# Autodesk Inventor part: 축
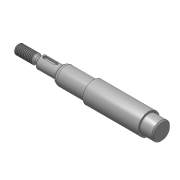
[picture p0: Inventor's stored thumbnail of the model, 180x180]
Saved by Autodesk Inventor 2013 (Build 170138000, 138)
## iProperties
Created: 2015-11
Part Number: 축
Material: 강철, 연강
Document SubType Name: Modeling
Designer: mduedu
Density: 1 g/cm^3
Author: mduedu
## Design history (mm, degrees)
sketch "스케치1"
  geometry: L1 (-86, 0)-(86, 0); L2 (-86, 0)-(-86, 4); L3 (-86, 4)-(-70.732, 4); L4 (-70.732, 4)-(-69, 3); L5 (-69, 3)-(-67, 3); L6 (-67, 3)-(-67, 5); L7 (-67, 5)-(-49, 5); L8 (-49, 5)-(-49, 6.55); L9 (-47.355, 7.5)-(-23, 7.5); L10 (-23, 7.5)-(-23, 9); L11 (0, 0)-(0, 9); L12 (86, 4)-(70.732, 4); L13 (70.732, 4)-(69, 3); L14 (69, 3)-(67, 3); L15 (67, 3)-(67, 5); L16 (67, 5)-(49, 5); L17 (23, 7.5)-(23, 9); L18 (86, 0)-(86, 4); L19 (-23, 9)-(23, 9); L20 (-49, 6.55)-(-47.355, 7.5); L21 (47.355, 7.5)-(23, 7.5); L22 (49, 6.55)-(47.355, 7.5); L23 (49, 5)-(49, 6.55); 1 further point
  constraints: 46 end point, 10 symmetric about line, 6 perpendicular, 5 parallel, 2 midpoint, 1 coincident, 1 horizontal
  dimensions: "d0" = 172 distance of L1.start L1.end (derived); "d1" = 8 diameter of L3 L1; "d2" = 30 deg angle of L4 L5; "d3" = 6 diameter of L5 L1; "d4" = 10 diameter of L7 L1; "d5" = 15 diameter of L9 L1; "d6" = 18 diameter of L19 L1; "d8" = 18 distance of L6.end L7.end; "d9" = 46 distance of L10.end L17.end; "d10" = 2 distance of L4.end L5.end; "d11" = 17 distance from line of L4.end L2; "d16" = 13.1 diameter of L8.end L1; "d17" = 30 deg angle of L20 L9; "d18" = 26 distance between parallel lines of L10 L8
revolve "회전1" sketch "스케치1" stored, may be unused: angle "d12" = 90 deg
chamfer "모따기1" distance "d13" = 1; stored, may be unused: second distance "d14" = 2, angle "d15" = 45 deg
fillet "모깎기3" dims "d35" = 4
node "작업 평면1"
sketch "스케치2" dims "d23" = 12
  geometry: L1 (-5.5, 1.5)-(3.5, 1.5); L2 (3.5, 1.5)-(3.5, -1.5); L3 (3.5, -1.5)-(-5.5, -1.5); L4 (-5.5, -1.5)-(-5.5, 1.5); L5 (-9, -4)-(-9, 4) reference; 3 further points
  constraints: 8 end point, 2 midpoint, 2 parallel, 2 vertical alignment, 1 horizontal, 1 perpendicular, 4 other
  dimensions: "d21" = 3 distance between parallel lines of L3 L1; "d24" = 2 dimension on L5
extrude "돌출1" cut sketch "스케치2" distance "d25" = 1.8; taper "d26" = 0 deg
feature "스레드1" dims "d27" = 10, "d28" = 0
feature "스레드2" dims "d29" = 10, "d30" = 0
chamfer "모따기2" distance "d31" = 1; stored, may be unused: second distance "d32" = 2, angle "d33" = 45 deg
fillet "모깎기2" dims "d34" = 0.3
node "작업 평면2"
sketch "스케치3"
  geometry: C1 r 7.5 at (0, 0) reference; 1 further point
extrude "돌출2" cut sketch "스케치3" stored distance "d37" = 10; taper "d38" = 0 deg
chamfer "모따기3" distance "d39" = 1; stored, may be unused: second distance "d40" = 2, angle "d41" = 45 deg
node "솔리드1"
mirror "대칭1"
node "절단 모서리 투영1"
other parameters: "d36" = 11
